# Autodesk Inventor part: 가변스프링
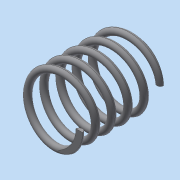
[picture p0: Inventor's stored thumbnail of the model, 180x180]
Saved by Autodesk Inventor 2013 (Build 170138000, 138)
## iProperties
Created: 2017-12
Part Number: 가변스프링
Material: 일반
Document SubType Name: Modeling
Designer: dgall
Density: 1 g/cm^3
Mass: 0.870953 g
Surface Area: 17.7103 cm^2
Volume: 0.870953 cm^3
Author: dgall
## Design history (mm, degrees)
sketch "스케치1"
  geometry: L1 (0, 0)-(9, 0); L2 (0, 0)-(0, 24.491); L3 (0, 24.491)-(9, 24.491); C1 r 1 at (9, 0)
  constraints: 6 end point, 2 perpendicular, 1 centre point, 1 coincident, 1 horizontal
  dimensions: "d0" = 18 diameter of L1.end L2; "d2" = 2 diameter of C1; "d3" = 24.49053 distance of L1.start L2.end (derived)
feature "코일1" sketch "스케치1" pitch "d4" = 10; turns "d6" = 5; dims "d5" = 24.49053 (= d3), "d7" = 0, angle "d8" = 90 deg, angle "d9" = 90 deg, "d10" = 0, "d11" = 0
node "작업 평면1"
node "작업 평면2"
feature "분할1"
feature "분할2"
node "솔리드1"
other parameters: "d12" = 0, "d13" = 0
